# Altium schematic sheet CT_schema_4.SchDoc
size 293 x 258 mm
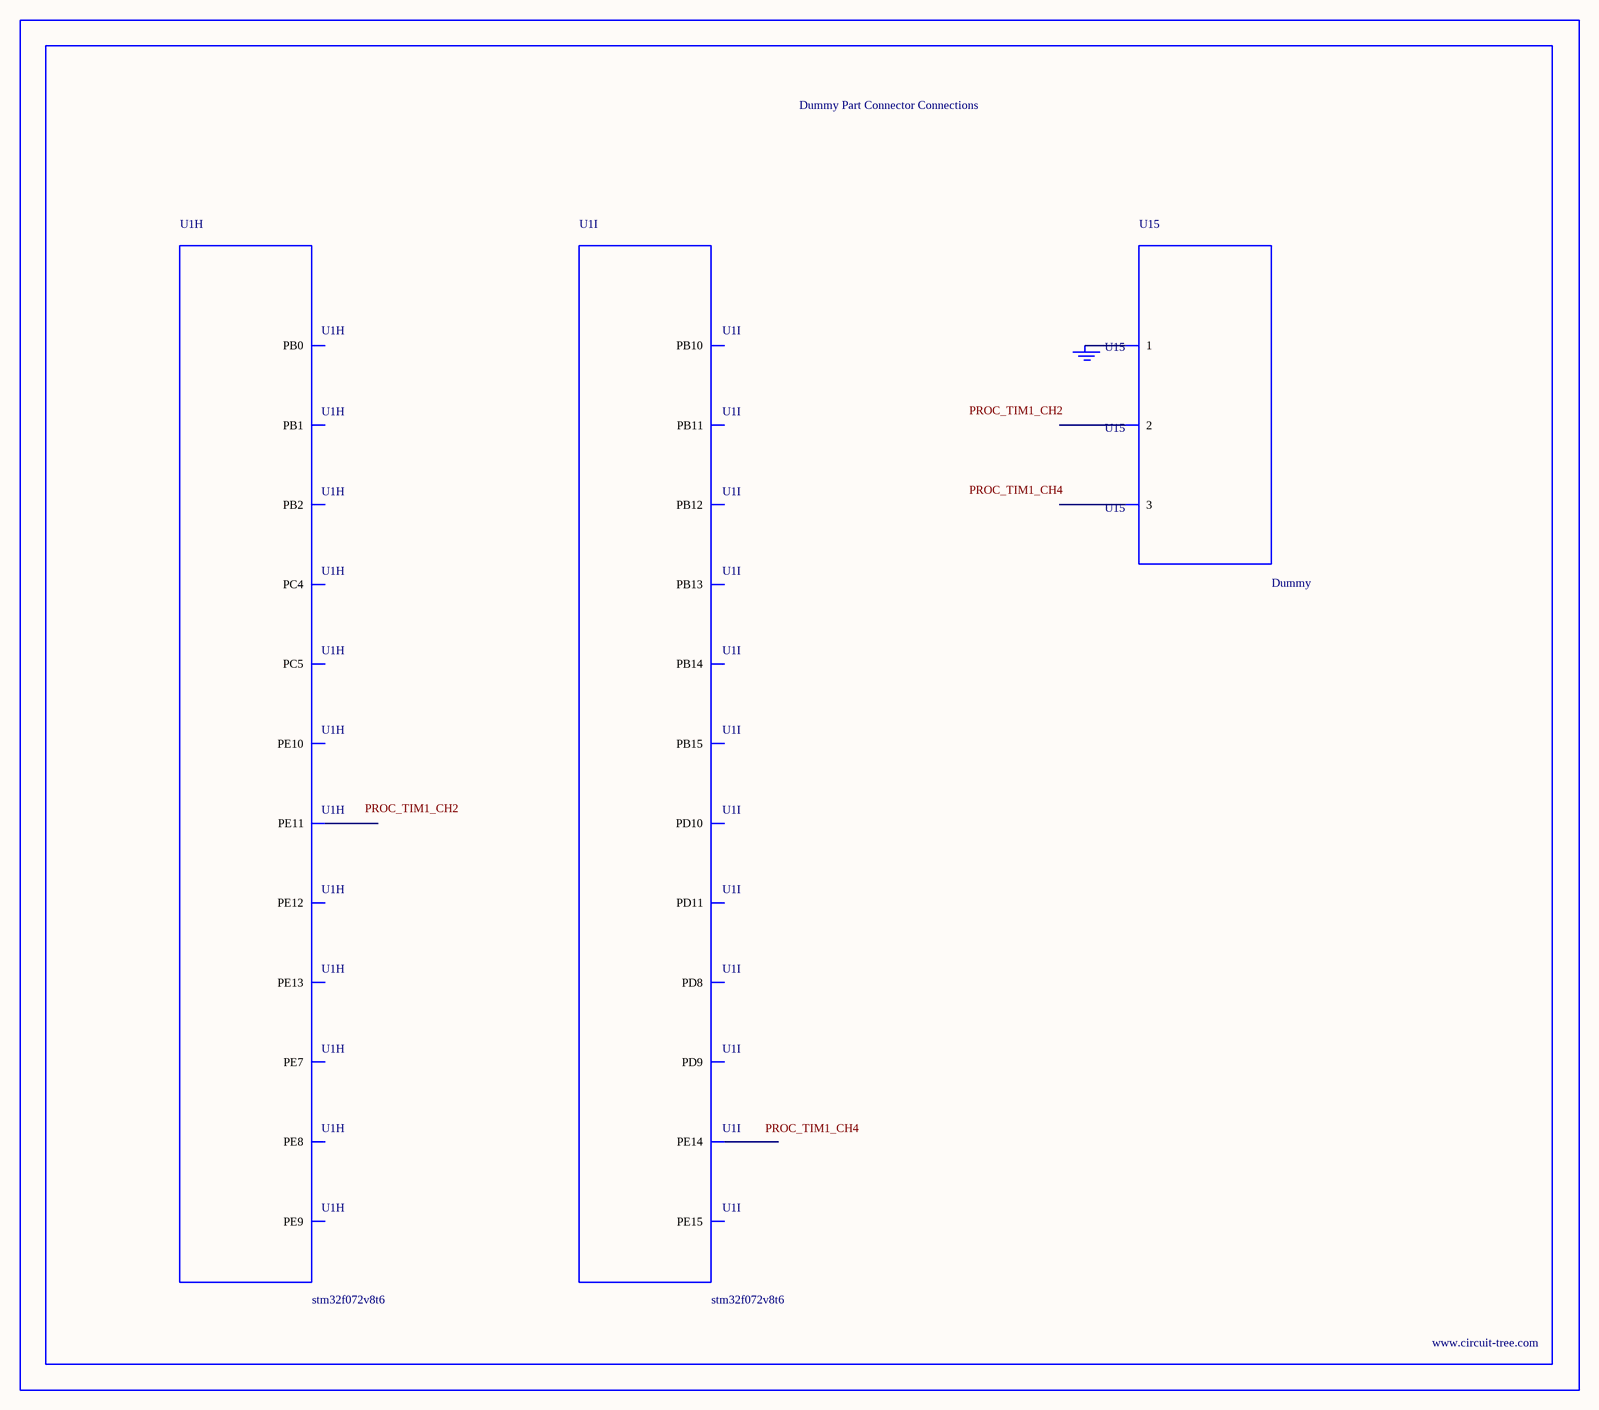
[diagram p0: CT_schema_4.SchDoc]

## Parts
BORDER3  (no value)
GND_INSTANCE_3_0  (no value)
U1  stm32f072v8t6  [LQFP100]  (parts H,I of 9)
U15  Dummy  [DUMMY_PACKAGE_119]

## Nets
NetGND_INSTANCE_3_0_0: GND_INSTANCE_3_0.0(GND) U15.1

Not connected (* = marked no-connect by the designer): U1 33(PC4) 34(PC5) 35(PB0) 36(PB1) 37(PB2) 38(PE7) 39(PE8) 40(PE9) 41(PE10) 42(PE11) 43(PE12) 44(PE13) 45(PE14) 46(PE15) 47(PB10) 48(PB11) 51(PB12) 52(PB13) 53(PB14) 54(PB15) 55(PD8) 56(PD9) 57(PD10) 58(PD11); U15 2 3

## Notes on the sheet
- Labels drawn without touching a wire or pin: PROC_TIM1_CH2, PROC_TIM1_CH4

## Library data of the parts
BORDER3 = BORDER_PAGE3
GND_INSTANCE_3_0 = GND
